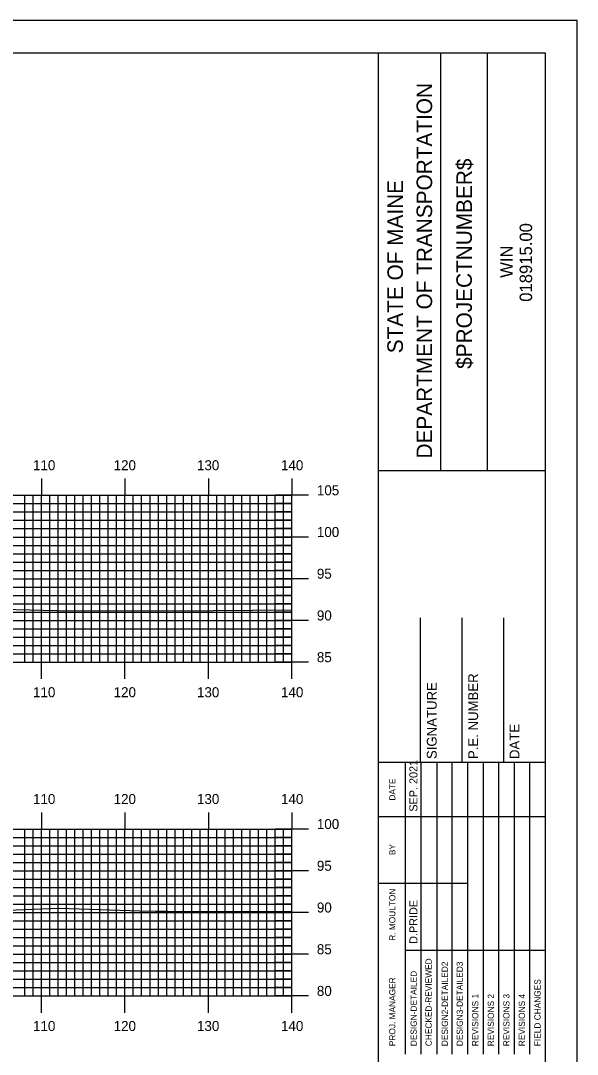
# Model space of a CAD drawing. Extents: x 1777925 to 1778268, y 442591 to 442811.
# Drawn here: x 1778198.3 to 1778265, y 442686.7 to 442810.5 of the extents above; entities that cross this region are included whole.
import ezdxf

# ---------------------------------------------------------------- set-up
doc = ezdxf.new("R2010")
doc.units = 0
for name, color, linetype in [('BORDER', 7, 'Continuous'), ('H_V ANNOTATION', 7, 'Continuous'), ('MAJOR', 7, 'Continuous'), ('MINOR', 7, 'Continuous'), ('PLOT BOUNDARY', 7, 'Continuous'), ('S_Roadway_Centerline', 7, 'Continuous')]:
    doc.layers.add(name, color=color, linetype=linetype)

msp = doc.modelspace()

# ---------------------------------------------------------------- linework, layer by layer
at = {"layer": 'BORDER'}
for p, q in [((1778241.19, 442596.67), (1778241.19, 442806.67)), ((1778248.65, 442756.66), (1778248.65, 442806.66)), ((1778254.24, 442756.66), (1778254.24, 442806.66)), ((1778241.19, 442756.65), (1778261.19, 442756.65)), ((1778246.19, 442721.67), (1778246.19, 442738.97)), ((1778251.19, 442721.67), (1778251.19, 442738.97)), ((1778256.19, 442721.67), (1778256.19, 442738.97)), ((1778241.19, 442721.67), (1778261.19, 442721.67))]:
    msp.add_line(p, q, dxfattribs=at)
msp.add_lwpolyline([(1777941.19, 442596.67), (1778261.19, 442596.67), (1778261.19, 442806.67), (1777941.19, 442806.67)], close=True, dxfattribs=at)
for points in [[(1778244.42, 442715.17), (1778244.42, 442721.67)], [(1778246.28, 442686.68), (1778246.28, 442721.67)], [(1778248.15, 442721.67), (1778248.15, 442686.68)], [(1778250.01, 442686.68), (1778250.01, 442721.67)], [(1778251.87, 442686.68), (1778251.87, 442721.67)], [(1778253.74, 442686.68), (1778253.74, 442721.67)], [(1778255.6, 442686.68), (1778255.6, 442721.67)], [(1778257.47, 442686.68), (1778257.47, 442721.67)], [(1778259.33, 442686.68), (1778259.33, 442721.67)], [(1778244.42, 442686.68), (1778244.42, 442720.26)], [(1778241.19, 442715.17), (1778261.19, 442715.17)], [(1778241.19, 442707.17), (1778244.42, 442707.17)], [(1778244.42, 442707.17), (1778251.87, 442707.17)], [(1778244.42, 442699.17), (1778261.19, 442699.17)]]:
    msp.add_lwpolyline(points, dxfattribs=at)
at = {"layer": 'MAJOR'}
for p, q in [((1778200.79, 442755.67), (1778200.79, 442753.67)), ((1778210.79, 442755.67), (1778210.79, 442753.67)), ((1778220.79, 442755.67), (1778220.79, 442753.67)), ((1778230.79, 442755.67), (1778230.79, 442753.67)), ((1777950.79, 442753.67), (1778230.79, 442753.67)), ((1777950.79, 442753.67), (1778230.79, 442753.67)), ((1778200.79, 442733.67), (1778200.79, 442753.67)), ((1778210.79, 442733.67), (1778210.79, 442753.67)), ((1778220.79, 442733.67), (1778220.79, 442753.67)), ((1778232.79, 442753.67), (1778228.79, 442753.67)), ((1778230.79, 442733.67), (1778230.79, 442753.67)), ((1778230.79, 442733.67), (1778230.79, 442753.67)), ((1777950.79, 442748.67), (1778230.79, 442748.67)), ((1778232.79, 442748.67), (1778228.79, 442748.67)), ((1777950.79, 442743.67), (1778230.79, 442743.67)), ((1778232.79, 442743.67), (1778228.79, 442743.67)), ((1777950.79, 442738.67), (1778230.79, 442738.67)), ((1778232.79, 442738.67), (1778228.79, 442738.67)), ((1777950.79, 442733.67), (1778230.79, 442733.67)), ((1777950.79, 442733.67), (1778230.79, 442733.67)), ((1778200.79, 442731.66), (1778200.79, 442733.67)), ((1778210.79, 442731.66), (1778210.79, 442733.67)), ((1778220.79, 442731.66), (1778220.79, 442733.67)), ((1778232.79, 442733.67), (1778228.79, 442733.67)), ((1778230.79, 442731.66), (1778230.79, 442733.67)), ((1778200.79, 442715.67), (1778200.79, 442713.67)), ((1778210.79, 442715.67), (1778210.79, 442713.67)), ((1778220.79, 442715.67), (1778220.79, 442713.67)), ((1778230.79, 442715.67), (1778230.79, 442713.67)), ((1777950.79, 442713.67), (1778230.79, 442713.67)), ((1777950.79, 442713.67), (1778230.79, 442713.67)), ((1778200.79, 442693.67), (1778200.79, 442713.67)), ((1778210.79, 442693.67), (1778210.79, 442713.67)), ((1778220.79, 442693.67), (1778220.79, 442713.67)), ((1778232.79, 442713.67), (1778228.79, 442713.67)), ((1778230.79, 442693.67), (1778230.79, 442713.67)), ((1778230.79, 442693.67), (1778230.79, 442713.67)), ((1777950.79, 442708.67), (1778230.79, 442708.67)), ((1778232.79, 442708.67), (1778228.79, 442708.67)), ((1777950.79, 442703.67), (1778230.79, 442703.67)), ((1778232.79, 442703.67), (1778228.79, 442703.67)), ((1777950.79, 442698.67), (1778230.79, 442698.67)), ((1778232.79, 442698.67), (1778228.79, 442698.67)), ((1777950.79, 442693.67), (1778230.79, 442693.67)), ((1777950.79, 442693.67), (1778230.79, 442693.67)), ((1778200.79, 442691.66), (1778200.79, 442693.67)), ((1778210.79, 442691.66), (1778210.79, 442693.67)), ((1778220.79, 442691.66), (1778220.79, 442693.67)), ((1778232.79, 442693.67), (1778228.79, 442693.67)), ((1778230.79, 442691.66), (1778230.79, 442693.67))]:
    msp.add_line(p, q, dxfattribs=at)
at = {"layer": 'MINOR'}
for p, q in [((1778198.79, 442733.67), (1778198.79, 442753.67)), ((1778199.79, 442733.67), (1778199.79, 442753.67)), ((1778201.79, 442733.67), (1778201.79, 442753.67)), ((1778202.79, 442733.67), (1778202.79, 442753.67)), ((1778203.79, 442733.67), (1778203.79, 442753.67)), ((1778204.79, 442733.67), (1778204.79, 442753.67)), ((1778205.79, 442733.67), (1778205.79, 442753.67)), ((1778206.79, 442733.67), (1778206.79, 442753.67)), ((1778207.79, 442733.67), (1778207.79, 442753.67)), ((1778208.79, 442733.67), (1778208.79, 442753.67)), ((1778209.79, 442733.67), (1778209.79, 442753.67)), ((1778211.79, 442733.67), (1778211.79, 442753.67)), ((1778212.79, 442733.67), (1778212.79, 442753.67)), ((1778213.79, 442733.67), (1778213.79, 442753.67)), ((1778214.79, 442733.67), (1778214.79, 442753.67)), ((1778215.79, 442733.67), (1778215.79, 442753.67)), ((1778216.79, 442733.67), (1778216.79, 442753.67)), ((1778217.79, 442733.67), (1778217.79, 442753.67)), ((1778218.79, 442733.67), (1778218.79, 442753.67)), ((1778219.79, 442733.67), (1778219.79, 442753.67)), ((1778221.79, 442733.67), (1778221.79, 442753.67)), ((1778222.79, 442733.67), (1778222.79, 442753.67)), ((1778223.79, 442733.67), (1778223.79, 442753.67)), ((1778224.79, 442733.67), (1778224.79, 442753.67)), ((1778225.79, 442733.67), (1778225.79, 442753.67)), ((1778226.79, 442733.67), (1778226.79, 442753.67)), ((1778227.79, 442733.67), (1778227.79, 442753.67)), ((1778228.79, 442733.67), (1778228.79, 442753.67)), ((1778229.79, 442733.67), (1778229.79, 442753.67)), ((1777950.79, 442752.67), (1778230.79, 442752.67)), ((1778230.79, 442752.67), (1778228.79, 442752.67)), ((1777950.79, 442751.67), (1778230.79, 442751.67)), ((1778230.79, 442751.67), (1778228.79, 442751.67)), ((1777950.79, 442750.67), (1778230.79, 442750.67)), ((1778230.79, 442750.67), (1778228.79, 442750.67)), ((1777950.79, 442749.67), (1778230.79, 442749.67)), ((1778230.79, 442749.67), (1778228.79, 442749.67)), ((1777950.79, 442747.67), (1778230.79, 442747.67)), ((1778230.79, 442747.67), (1778228.79, 442747.67)), ((1777950.79, 442746.67), (1778230.79, 442746.67)), ((1778230.79, 442746.67), (1778228.79, 442746.67)), ((1777950.79, 442745.67), (1778230.79, 442745.67)), ((1778230.79, 442745.67), (1778228.79, 442745.67)), ((1777950.79, 442744.67), (1778230.79, 442744.67)), ((1778230.79, 442744.67), (1778228.79, 442744.67)), ((1777950.79, 442742.67), (1778230.79, 442742.67)), ((1778230.79, 442742.67), (1778228.79, 442742.67)), ((1777950.79, 442741.67), (1778230.79, 442741.67)), ((1778230.79, 442741.67), (1778228.79, 442741.67)), ((1777950.79, 442740.67), (1778230.79, 442740.67)), ((1778230.79, 442740.67), (1778228.79, 442740.67)), ((1777950.79, 442739.67), (1778230.79, 442739.67)), ((1778230.79, 442739.67), (1778228.79, 442739.67)), ((1777950.79, 442737.67), (1778230.79, 442737.67)), ((1778230.79, 442737.67), (1778228.79, 442737.67)), ((1777950.79, 442736.67), (1778230.79, 442736.67)), ((1778230.79, 442736.67), (1778228.79, 442736.67)), ((1777950.79, 442735.67), (1778230.79, 442735.67)), ((1778230.79, 442735.67), (1778228.79, 442735.67)), ((1777950.79, 442734.67), (1778230.79, 442734.67)), ((1778230.79, 442734.67), (1778228.79, 442734.67)), ((1778198.79, 442693.67), (1778198.79, 442713.67)), ((1778199.79, 442693.67), (1778199.79, 442713.67)), ((1778201.79, 442693.67), (1778201.79, 442713.67)), ((1778202.79, 442693.67), (1778202.79, 442713.67)), ((1778203.79, 442693.67), (1778203.79, 442713.67)), ((1778204.79, 442693.67), (1778204.79, 442713.67)), ((1778205.79, 442693.67), (1778205.79, 442713.67)), ((1778206.79, 442693.67), (1778206.79, 442713.67)), ((1778207.79, 442693.67), (1778207.79, 442713.67)), ((1778208.79, 442693.67), (1778208.79, 442713.67)), ((1778209.79, 442693.67), (1778209.79, 442713.67)), ((1778211.79, 442693.67), (1778211.79, 442713.67)), ((1778212.79, 442693.67), (1778212.79, 442713.67)), ((1778213.79, 442693.67), (1778213.79, 442713.67)), ((1778214.79, 442693.67), (1778214.79, 442713.67)), ((1778215.79, 442693.67), (1778215.79, 442713.67)), ((1778216.79, 442693.67), (1778216.79, 442713.67)), ((1778217.79, 442693.67), (1778217.79, 442713.67)), ((1778218.79, 442693.67), (1778218.79, 442713.67)), ((1778219.79, 442693.67), (1778219.79, 442713.67)), ((1778221.79, 442693.67), (1778221.79, 442713.67)), ((1778222.79, 442693.67), (1778222.79, 442713.67)), ((1778223.79, 442693.67), (1778223.79, 442713.67)), ((1778224.79, 442693.67), (1778224.79, 442713.67)), ((1778225.79, 442693.67), (1778225.79, 442713.67)), ((1778226.79, 442693.67), (1778226.79, 442713.67)), ((1778227.79, 442693.67), (1778227.79, 442713.67)), ((1778228.79, 442693.67), (1778228.79, 442713.67)), ((1778229.79, 442693.67), (1778229.79, 442713.67)), ((1777950.79, 442712.67), (1778230.79, 442712.67)), ((1777950.79, 442711.67), (1778230.79, 442711.67)), ((1778230.79, 442712.67), (1778228.79, 442712.67)), ((1778230.79, 442711.67), (1778228.79, 442711.67)), ((1777950.79, 442710.67), (1778230.79, 442710.67)), ((1778230.79, 442710.67), (1778228.79, 442710.67)), ((1777950.79, 442709.67), (1778230.79, 442709.67)), ((1778230.79, 442709.67), (1778228.79, 442709.67)), ((1777950.79, 442707.67), (1778230.79, 442707.67)), ((1777950.79, 442706.67), (1778230.79, 442706.67)), ((1778230.79, 442707.67), (1778228.79, 442707.67)), ((1778230.79, 442706.67), (1778228.79, 442706.67)), ((1777950.79, 442705.67), (1778230.79, 442705.67)), ((1778230.79, 442705.67), (1778228.79, 442705.67)), ((1777950.79, 442704.67), (1778230.79, 442704.67)), ((1778230.79, 442704.67), (1778228.79, 442704.67)), ((1777950.79, 442702.67), (1778230.79, 442702.67)), ((1777950.79, 442701.67), (1778230.79, 442701.67)), ((1778230.79, 442702.67), (1778228.79, 442702.67)), ((1778230.79, 442701.67), (1778228.79, 442701.67)), ((1777950.79, 442700.67), (1778230.79, 442700.67)), ((1778230.79, 442700.67), (1778228.79, 442700.67)), ((1777950.79, 442699.67), (1778230.79, 442699.67)), ((1778230.79, 442699.67), (1778228.79, 442699.67)), ((1777950.79, 442697.67), (1778230.79, 442697.67)), ((1777950.79, 442696.67), (1778230.79, 442696.67)), ((1778230.79, 442697.67), (1778228.79, 442697.67)), ((1778230.79, 442696.67), (1778228.79, 442696.67)), ((1777950.79, 442695.67), (1778230.79, 442695.67)), ((1778230.79, 442695.67), (1778228.79, 442695.67)), ((1777950.79, 442694.67), (1778230.79, 442694.67)), ((1778230.79, 442694.67), (1778228.79, 442694.67))]:
    msp.add_line(p, q, dxfattribs=at)
at = {"layer": 'PLOT BOUNDARY'}
msp.add_lwpolyline([(1777925, 442590.55), (1778265, 442590.55), (1778265, 442810.55), (1777925, 442810.55)], close=True, dxfattribs=at)
at = {"layer": 'S_Roadway_Centerline'}
for points in [[(1778123.36, 442740.3), (1778145.53, 442740.27), (1778145.73, 442740.27), (1778145.89, 442740.27), (1778150.39, 442740.14), (1778168.29, 442739.64), (1778169.47, 442739.68), (1778190.9, 442740.15), (1778191.09, 442740.14), (1778191.28, 442740.13), (1778204.21, 442739.83), (1778215.3, 442739.86), (1778216.68, 442739.84), (1778230.79, 442739.93)], [(1778126.6, 442703.95), (1778139.24, 442703.73), (1778143.63, 442703.67), (1778148.35, 442703.69), (1778156.61, 442704.07), (1778164.36, 442704.07), (1778172.11, 442704.17), (1778187.34, 442703.88), (1778194.63, 442703.89), (1778202.89, 442704.19), (1778212.57, 442703.88), (1778214.5, 442703.84), (1778215.91, 442703.84), (1778230.79, 442703.79)]]:
    msp.add_lwpolyline(points, dxfattribs=at)

# ---------------------------------------------------------------- texts
at = {"layer": 'BORDER'}
for s, height, p in [('DEPARTMENT OF TRANSPORTATION', 1.8635, (1778247.6, 442758.08)), ('$PROJECTNUMBER$', 1.8635, (1778252.37, 442768.82)), ('STATE OF MAINE', 1.8635, (1778244.1, 442770.69)), ('018915.00', 1.491, (1778259.58, 442776.86)), ('WIN', 1.491, (1778257.26, 442779.73)), ('P.E. NUMBER', 1.1811, (1778253.11, 442722.06)), ('SIGNATURE', 1.181, (1778248.15, 442722.06)), ('DATE', 1.181, (1778258.07, 442722.06)), ('SEP. 2021', 0.969, (1778245.84, 442715.76)), ('DATE', 0.743, (1778243.2, 442717.08)), ('BY', 0.743, (1778243.2, 442710.54)), ('R. MOULTON', 0.745, (1778243.2, 442700.28)), ('D.PRIDE', 0.969, (1778245.84, 442699.92)), ('CHECKED-REVIEWED', 0.7455, (1778247.55, 442687.65)), ('DESIGN2-DETAILED2', 0.7455, (1778249.49, 442687.65)), ('DESIGN3-DETAILED3', 0.7455, (1778251.28, 442687.65)), ('PROJ. MANAGER', 0.7455, (1778243.2, 442687.65)), ('DESIGN-DETAILED', 0.7455, (1778245.76, 442687.65)), ('FIELD CHANGES', 0.7455, (1778260.6, 442687.65)), ('REVISIONS 1', 0.7455, (1778253.14, 442687.65)), ('REVISIONS 2', 0.7455, (1778255.01, 442687.65)), ('REVISIONS 3', 0.7455, (1778256.87, 442687.65)), ('REVISIONS 4', 0.7455, (1778258.73, 442687.65))]:
    msp.add_text(s, height=height, rotation=90, dxfattribs=at).set_placement(p)
at = {"layer": 'H_V ANNOTATION'}
for s, p in [('110', (1778199.77, 442756.67)), ('120', (1778209.43, 442756.67)), ('130', (1778219.42, 442756.67)), ('140', (1778229.49, 442756.67)), ('105', (1778233.79, 442753.67)), ('100', (1778233.79, 442748.67)), ('95', (1778233.79, 442743.67)), ('90', (1778233.79, 442738.67)), ('85', (1778233.79, 442733.67)), ('110', (1778199.77, 442729.47)), ('120', (1778209.43, 442729.47)), ('130', (1778219.42, 442729.47)), ('140', (1778229.49, 442729.47)), ('110', (1778199.77, 442716.67)), ('120', (1778209.43, 442716.67)), ('130', (1778219.42, 442716.67)), ('140', (1778229.49, 442716.67)), ('100', (1778233.79, 442713.67)), ('95', (1778233.79, 442708.67)), ('90', (1778233.79, 442703.67)), ('85', (1778233.79, 442698.67)), ('80', (1778233.79, 442693.67)), ('110', (1778199.77, 442689.47)), ('120', (1778209.43, 442689.47)), ('130', (1778219.42, 442689.47)), ('140', (1778229.49, 442689.47))]:
    msp.add_text(s, height=1.2, dxfattribs=at).set_placement(p)

doc.saveas('drawing.dxf')
